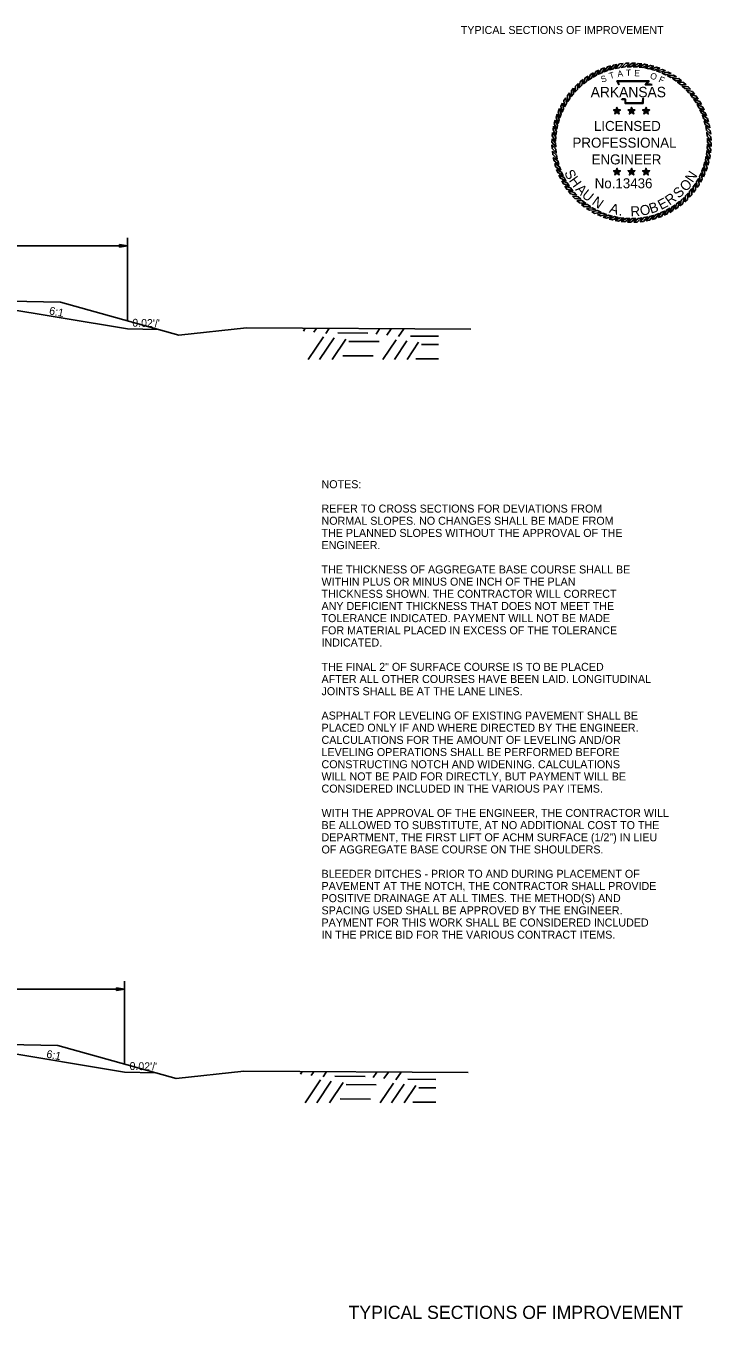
# Model space of a CAD drawing. Extents: x 1398565 to 1398920, y 1968324 to 1968581.
# Drawn here: x 1398868.6 to 1398919.9, y 1968325.3 to 1968422.2 of the extents above; entities that cross this region are included whole.
import ezdxf

# ---------------------------------------------------------------- set-up
doc = ezdxf.new("R2010")
doc.units = 0
for name, color, linetype in [('1', 7, 'Continuous'), ('10', 7, 'Continuous'), ('19', 7, 'Continuous'), ('42', 7, 'Continuous'), ('9', 7, 'Continuous'), ('G-ANNO-SYMB', 7, 'Continuous')]:
    doc.layers.add(name, color=color, linetype=linetype)

msp = doc.modelspace()

# ---------------------------------------------------------------- linework, layer by layer
at = {"layer": '19'}
for p, q in [((1398854.176, 1968405.693), (1398876.176, 1968405.693)), ((1398875.576, 1968405.588), (1398875.576, 1968405.798)), ((1398875.576, 1968405.798), (1398876.176, 1968405.693)), ((1398875.576, 1968405.743), (1398876.016, 1968405.708)), ((1398876.176, 1968405.693), (1398875.576, 1968405.588)), ((1398876.016, 1968405.678), (1398875.576, 1968405.638)), ((1398876.176, 1968400.085), (1398876.176, 1968406.293)), ((1398862.176, 1968401.81), (1398876.176, 1968399.477)), ((1398878.492, 1968399.431), (1398876.176, 1968399.477)), ((1398875.969, 1968344.375), (1398875.969, 1968350.582)), ((1398853.969, 1968349.982), (1398875.969, 1968349.982)), ((1398875.369, 1968349.877), (1398875.369, 1968350.087)), ((1398875.369, 1968350.087), (1398875.969, 1968349.982)), ((1398875.369, 1968350.032), (1398875.809, 1968349.997)), ((1398875.969, 1968349.982), (1398875.369, 1968349.877)), ((1398875.809, 1968349.967), (1398875.369, 1968349.927)), ((1398861.969, 1968346.1), (1398875.969, 1968343.767)), ((1398878.286, 1968343.72), (1398875.969, 1968343.767))]:
    msp.add_line(p, q, dxfattribs=at)
at = {"layer": '42'}
for points in [[(1398854.176, 1968401.924), (1398862.261, 1968401.64), (1398871.176, 1968401.464), (1398880.031, 1968399.003), (1398885.112, 1968399.545), (1398901.928, 1968399.456)], [(1398853.969, 1968346.213), (1398862.054, 1968345.93), (1398870.969, 1968345.753), (1398879.824, 1968343.293), (1398884.905, 1968343.835), (1398901.722, 1968343.746)]]:
    msp.add_lwpolyline(points, dxfattribs=at)
at = {"layer": '9'}
for p, q in [((1398889.366, 1968399.313), (1398889.469, 1968399.467)), ((1398889.715, 1968397.173), (1398890.868, 1968398.889)), ((1398890.163, 1968399.221), (1398890.329, 1968399.468)), ((1398890.575, 1968397.174), (1398891.666, 1968398.797)), ((1398891.053, 1968399.13), (1398891.282, 1968399.47)), ((1398891.527, 1968397.176), (1398892.556, 1968398.706)), ((1398891.943, 1968399.169), (1398894.205, 1968399.154)), ((1398894.817, 1968399.081), (1398895.083, 1968399.477)), ((1398895.328, 1968397.183), (1398896.32, 1968398.657)), ((1398895.615, 1968398.99), (1398895.943, 1968399.478)), ((1398896.505, 1968398.899), (1398896.895, 1968399.48)), ((1398897.394, 1968398.937), (1398899.5, 1968398.924)), ((1398892.779, 1968398.54), (1398895.041, 1968398.525)), ((1398896.188, 1968397.184), (1398897.117, 1968398.566)), ((1398897.141, 1968397.186), (1398898.007, 1968398.475)), ((1398898.23, 1968398.308), (1398899.501, 1968398.3)), ((1398892.336, 1968397.463), (1398894.597, 1968397.449)), ((1398897.787, 1968397.231), (1398899.503, 1968397.22)), ((1398889.159, 1968343.603), (1398889.263, 1968343.757)), ((1398889.957, 1968343.511), (1398890.123, 1968343.758)), ((1398890.847, 1968343.42), (1398891.075, 1968343.76)), ((1398891.737, 1968343.459), (1398893.999, 1968343.444)), ((1398894.611, 1968343.371), (1398894.876, 1968343.766)), ((1398895.408, 1968343.28), (1398895.736, 1968343.768)), ((1398896.298, 1968343.188), (1398896.689, 1968343.769)), ((1398889.508, 1968341.463), (1398890.662, 1968343.179)), ((1398890.368, 1968341.464), (1398891.459, 1968343.087)), ((1398891.321, 1968341.466), (1398892.349, 1968342.996)), ((1398892.572, 1968342.829), (1398894.834, 1968342.815)), ((1398895.122, 1968341.472), (1398896.113, 1968342.947)), ((1398895.982, 1968341.474), (1398896.911, 1968342.855)), ((1398896.934, 1968341.476), (1398897.801, 1968342.764)), ((1398897.188, 1968343.227), (1398899.294, 1968343.213)), ((1398898.023, 1968342.598), (1398899.295, 1968342.59)), ((1398892.129, 1968341.753), (1398894.391, 1968341.738)), ((1398897.58, 1968341.521), (1398899.297, 1968341.51))]:
    msp.add_line(p, q, dxfattribs=at)
at = {"layer": 'G-ANNO-SYMB'}
for points in [[(1398911.959, 1968419.05), (1398911.719, 1968418.958), (1398911.494, 1968418.56), (1398911.746, 1968418.674)], [(1398912.406, 1968419.19), (1398912.16, 1968419.117), (1398911.904, 1968418.738), (1398912.165, 1968418.832)], [(1398912.862, 1968419.294), (1398912.611, 1968419.241), (1398912.327, 1968418.883), (1398912.594, 1968418.957)], [(1398913.326, 1968419.362), (1398913.071, 1968419.329), (1398912.76, 1968418.995), (1398913.032, 1968419.047)], [(1398913.793, 1968419.394), (1398913.537, 1968419.381), (1398913.2, 1968419.072), (1398913.475, 1968419.103)], [(1398914.262, 1968419.389), (1398914.005, 1968419.396), (1398913.645, 1968419.115), (1398913.922, 1968419.124)], [(1398914.728, 1968419.347), (1398914.473, 1968419.375), (1398914.092, 1968419.122), (1398914.369, 1968419.109)], [(1398915.19, 1968419.269), (1398914.938, 1968419.316), (1398914.538, 1968419.095), (1398914.813, 1968419.06)], [(1398915.644, 1968419.155), (1398915.397, 1968419.222), (1398914.981, 1968419.032), (1398915.252, 1968418.976)], [(1398916.088, 1968419.005), (1398915.847, 1968419.092), (1398915.417, 1968418.935), (1398915.683, 1968418.858)], [(1398910.321, 1968418.155), (1398910.121, 1968417.994), (1398910.03, 1968417.546), (1398910.235, 1968417.732)], [(1398910.702, 1968418.426), (1398910.491, 1968418.281), (1398910.365, 1968417.842), (1398910.584, 1968418.012)], [(1398911.104, 1968418.667), (1398910.882, 1968418.539), (1398910.722, 1968418.111), (1398910.953, 1968418.263)], [(1398911.524, 1968418.875), (1398911.292, 1968418.765), (1398911.099, 1968418.351), (1398911.342, 1968418.484)], [(1398916.519, 1968418.822), (1398916.285, 1968418.926), (1398915.844, 1968418.804), (1398916.104, 1968418.706)], [(1398916.934, 1968418.604), (1398916.709, 1968418.727), (1398916.26, 1968418.64), (1398916.511, 1968418.522)], [(1398917.331, 1968418.355), (1398917.116, 1968418.496), (1398916.662, 1968418.444), (1398916.903, 1968418.307)], [(1398917.707, 1968418.076), (1398917.504, 1968418.233), (1398917.047, 1968418.217), (1398917.276, 1968418.061)], [(1398909.318, 1968417.174), (1398909.162, 1968416.971), (1398909.178, 1968416.514), (1398909.333, 1968416.743)], [(1398909.626, 1968417.527), (1398909.454, 1968417.337), (1398909.434, 1968416.88), (1398909.608, 1968417.096)], [(1398909.961, 1968417.855), (1398909.775, 1968417.678), (1398909.719, 1968417.224), (1398909.909, 1968417.427)], [(1398918.06, 1968417.768), (1398917.87, 1968417.94), (1398917.413, 1968417.96), (1398917.629, 1968417.787)], [(1398918.388, 1968417.433), (1398918.212, 1968417.62), (1398917.758, 1968417.675), (1398917.96, 1968417.486)], [(1398918.688, 1968417.074), (1398918.527, 1968417.274), (1398918.079, 1968417.365), (1398918.266, 1968417.16)], [(1398918.959, 1968416.692), (1398918.815, 1968416.904), (1398918.375, 1968417.03), (1398918.545, 1968416.811)], [(1398908.79, 1968416.401), (1398908.667, 1968416.176), (1398908.754, 1968415.727), (1398908.872, 1968415.978)], [(1398909.039, 1968416.798), (1398908.899, 1968416.583), (1398908.95, 1968416.129), (1398909.088, 1968416.37)], [(1398912.873, 1968415.806), (1398912.934, 1968415.891), (1398912.873, 1968416.079), (1398912.812, 1968415.891)], [(1398913.964, 1968415.806), (1398914.025, 1968415.891), (1398913.964, 1968416.079), (1398913.903, 1968415.891)], [(1398915.055, 1968415.806), (1398915.116, 1968415.891), (1398915.055, 1968416.079), (1398914.993, 1968415.891)], [(1398919.2, 1968416.29), (1398919.072, 1968416.512), (1398918.644, 1968416.672), (1398918.796, 1968416.441)], [(1398919.408, 1968415.87), (1398919.298, 1968416.102), (1398918.884, 1968416.295), (1398919.017, 1968416.052)], [(1398908.239, 1968415.111), (1398908.172, 1968414.864), (1398908.362, 1968414.447), (1398908.418, 1968414.719)], [(1398908.389, 1968415.555), (1398908.303, 1968415.314), (1398908.459, 1968414.884), (1398908.536, 1968415.15)], [(1398908.573, 1968415.986), (1398908.468, 1968415.752), (1398908.59, 1968415.311), (1398908.688, 1968415.571)], [(1398912.873, 1968415.806), (1398912.812, 1968415.891), (1398912.613, 1968415.891), (1398912.774, 1968415.774)], [(1398912.873, 1968415.806), (1398912.774, 1968415.774), (1398912.713, 1968415.586), (1398912.873, 1968415.702)], [(1398912.873, 1968415.806), (1398912.972, 1968415.774), (1398913.132, 1968415.891), (1398912.934, 1968415.891)], [(1398912.873, 1968415.806), (1398912.873, 1968415.702), (1398913.033, 1968415.586), (1398912.972, 1968415.774)], [(1398913.964, 1968415.806), (1398913.903, 1968415.891), (1398913.704, 1968415.891), (1398913.865, 1968415.774)], [(1398913.964, 1968415.806), (1398913.865, 1968415.774), (1398913.803, 1968415.586), (1398913.964, 1968415.702)], [(1398913.964, 1968415.806), (1398914.063, 1968415.774), (1398914.223, 1968415.891), (1398914.025, 1968415.891)], [(1398913.964, 1968415.806), (1398913.964, 1968415.702), (1398914.124, 1968415.586), (1398914.063, 1968415.774)], [(1398915.055, 1968415.806), (1398914.993, 1968415.891), (1398914.795, 1968415.891), (1398914.956, 1968415.774)], [(1398915.055, 1968415.806), (1398914.956, 1968415.774), (1398914.894, 1968415.586), (1398915.055, 1968415.702)], [(1398915.055, 1968415.806), (1398915.154, 1968415.774), (1398915.314, 1968415.891), (1398915.116, 1968415.891)], [(1398915.055, 1968415.806), (1398915.055, 1968415.702), (1398915.215, 1968415.586), (1398915.154, 1968415.774)], [(1398919.583, 1968415.436), (1398919.491, 1968415.675), (1398919.093, 1968415.9), (1398919.207, 1968415.648)], [(1398919.723, 1968414.989), (1398919.65, 1968415.235), (1398919.271, 1968415.49), (1398919.365, 1968415.23)], [(1398908.047, 1968414.195), (1398908.02, 1968413.94), (1398908.272, 1968413.559), (1398908.285, 1968413.836)], [(1398908.125, 1968414.657), (1398908.078, 1968414.405), (1398908.3, 1968414.005), (1398908.334, 1968414.28)], [(1398919.827, 1968414.532), (1398919.774, 1968414.783), (1398919.417, 1968415.068), (1398919.49, 1968414.8)], [(1398919.895, 1968414.068), (1398919.863, 1968414.323), (1398919.528, 1968414.635), (1398919.58, 1968414.362)], [(1398919.927, 1968413.601), (1398919.914, 1968413.857), (1398919.605, 1968414.194), (1398919.636, 1968413.919)], [(1398908.005, 1968413.728), (1398907.998, 1968413.472), (1398908.279, 1968413.112), (1398908.271, 1968413.389)], [(1398908, 1968413.26), (1398908.013, 1968413.004), (1398908.322, 1968412.667), (1398908.292, 1968412.942)], [(1398919.881, 1968412.666), (1398919.908, 1968412.921), (1398919.656, 1968413.302), (1398919.643, 1968413.026)], [(1398919.922, 1968413.133), (1398919.93, 1968413.389), (1398919.648, 1968413.749), (1398919.657, 1968413.472)], [(1398908.032, 1968412.793), (1398908.065, 1968412.538), (1398908.399, 1968412.226), (1398908.347, 1968412.499)], [(1398908.1, 1968412.329), (1398908.153, 1968412.078), (1398908.511, 1968411.794), (1398908.438, 1968412.061)], [(1398919.688, 1968411.75), (1398919.755, 1968411.998), (1398919.565, 1968412.414), (1398919.509, 1968412.142)], [(1398919.802, 1968412.204), (1398919.85, 1968412.456), (1398919.628, 1968412.856), (1398919.593, 1968412.581)], [(1398908.205, 1968411.873), (1398908.277, 1968411.626), (1398908.656, 1968411.371), (1398908.562, 1968411.632)], [(1398908.345, 1968411.426), (1398908.436, 1968411.186), (1398908.834, 1968410.961), (1398908.72, 1968411.213)], [(1398912.873, 1968411.238), (1398912.812, 1968411.322), (1398912.613, 1968411.322), (1398912.774, 1968411.206)], [(1398912.873, 1968411.238), (1398912.774, 1968411.206), (1398912.713, 1968411.017), (1398912.873, 1968411.134)], [(1398912.873, 1968411.238), (1398912.934, 1968411.322), (1398912.873, 1968411.511), (1398912.812, 1968411.322)], [(1398912.873, 1968411.238), (1398912.972, 1968411.206), (1398913.132, 1968411.322), (1398912.934, 1968411.322)], [(1398912.873, 1968411.238), (1398912.873, 1968411.134), (1398913.033, 1968411.017), (1398912.972, 1968411.206)], [(1398913.964, 1968411.238), (1398913.903, 1968411.322), (1398913.704, 1968411.322), (1398913.865, 1968411.206)], [(1398913.964, 1968411.238), (1398913.865, 1968411.206), (1398913.803, 1968411.017), (1398913.964, 1968411.134)], [(1398913.964, 1968411.238), (1398914.025, 1968411.322), (1398913.964, 1968411.511), (1398913.903, 1968411.322)], [(1398913.964, 1968411.238), (1398914.063, 1968411.206), (1398914.223, 1968411.322), (1398914.025, 1968411.322)], [(1398913.964, 1968411.238), (1398913.964, 1968411.134), (1398914.124, 1968411.017), (1398914.063, 1968411.206)], [(1398915.055, 1968411.238), (1398914.993, 1968411.322), (1398914.795, 1968411.322), (1398914.956, 1968411.206)], [(1398915.055, 1968411.238), (1398914.956, 1968411.206), (1398914.894, 1968411.017), (1398915.055, 1968411.134)], [(1398915.055, 1968411.238), (1398915.116, 1968411.322), (1398915.055, 1968411.511), (1398914.993, 1968411.322)], [(1398915.055, 1968411.238), (1398915.154, 1968411.206), (1398915.314, 1968411.322), (1398915.116, 1968411.322)], [(1398915.055, 1968411.238), (1398915.055, 1968411.134), (1398915.215, 1968411.017), (1398915.154, 1968411.206)], [(1398919.355, 1968410.875), (1398919.46, 1968411.109), (1398919.337, 1968411.55), (1398919.239, 1968411.291)], [(1398919.539, 1968411.306), (1398919.625, 1968411.548), (1398919.468, 1968411.977), (1398919.391, 1968411.711)], [(1398908.519, 1968410.991), (1398908.629, 1968410.759), (1398909.044, 1968410.566), (1398908.91, 1968410.809)], [(1398908.728, 1968410.571), (1398908.855, 1968410.349), (1398909.284, 1968410.189), (1398909.131, 1968410.42)], [(1398918.609, 1968409.687), (1398918.766, 1968409.89), (1398918.75, 1968410.347), (1398918.594, 1968410.118)], [(1398918.889, 1968410.063), (1398919.029, 1968410.278), (1398918.977, 1968410.732), (1398918.84, 1968410.492)], [(1398919.138, 1968410.46), (1398919.26, 1968410.685), (1398919.173, 1968411.134), (1398919.055, 1968410.883)], [(1398908.968, 1968410.169), (1398909.113, 1968409.958), (1398909.553, 1968409.831), (1398909.383, 1968410.05)], [(1398909.239, 1968409.787), (1398909.4, 1968409.588), (1398909.848, 1968409.496), (1398909.662, 1968409.701)], [(1398909.54, 1968409.428), (1398909.716, 1968409.241), (1398910.17, 1968409.186), (1398909.968, 1968409.375)], [(1398917.607, 1968408.706), (1398917.807, 1968408.867), (1398917.898, 1968409.315), (1398917.693, 1968409.129)], [(1398917.966, 1968409.007), (1398918.153, 1968409.183), (1398918.209, 1968409.637), (1398918.019, 1968409.435)], [(1398918.301, 1968409.334), (1398918.473, 1968409.525), (1398918.493, 1968409.981), (1398918.32, 1968409.765)], [(1398909.867, 1968409.093), (1398910.058, 1968408.921), (1398910.515, 1968408.901), (1398910.298, 1968409.074)], [(1398910.22, 1968408.785), (1398910.424, 1968408.629), (1398910.881, 1968408.644), (1398910.651, 1968408.8)], [(1398910.596, 1968408.506), (1398910.811, 1968408.366), (1398911.266, 1968408.417), (1398911.025, 1968408.555)], [(1398910.993, 1968408.257), (1398911.218, 1968408.134), (1398911.667, 1968408.221), (1398911.416, 1968408.339)], [(1398915.969, 1968407.812), (1398916.208, 1968407.903), (1398916.434, 1968408.301), (1398916.181, 1968408.187)], [(1398916.403, 1968407.986), (1398916.635, 1968408.096), (1398916.828, 1968408.511), (1398916.586, 1968408.377)], [(1398916.823, 1968408.194), (1398917.046, 1968408.322), (1398917.206, 1968408.751), (1398916.974, 1968408.598)], [(1398917.225, 1968408.435), (1398917.437, 1968408.58), (1398917.563, 1968409.019), (1398917.344, 1968408.849)], [(1398911.408, 1968408.04), (1398911.642, 1968407.935), (1398912.083, 1968408.057), (1398911.824, 1968408.155)], [(1398911.839, 1968407.856), (1398912.081, 1968407.77), (1398912.51, 1968407.926), (1398912.244, 1968408.003)], [(1398912.283, 1968407.706), (1398912.531, 1968407.639), (1398912.947, 1968407.829), (1398912.675, 1968407.885)], [(1398912.737, 1968407.592), (1398912.99, 1968407.545), (1398913.389, 1968407.766), (1398913.114, 1968407.801)], [(1398913.199, 1968407.514), (1398913.454, 1968407.486), (1398913.836, 1968407.739), (1398913.559, 1968407.752)], [(1398913.666, 1968407.472), (1398913.922, 1968407.465), (1398914.283, 1968407.746), (1398914.006, 1968407.738)], [(1398914.134, 1968407.467), (1398914.39, 1968407.48), (1398914.728, 1968407.789), (1398914.452, 1968407.758)], [(1398914.602, 1968407.499), (1398914.856, 1968407.532), (1398915.168, 1968407.866), (1398914.896, 1968407.814)], [(1398915.065, 1968407.567), (1398915.316, 1968407.62), (1398915.601, 1968407.978), (1398915.333, 1968407.905)], [(1398915.522, 1968407.672), (1398915.768, 1968407.744), (1398916.024, 1968408.123), (1398915.763, 1968408.029)]]:
    msp.add_lwpolyline(points, close=True, dxfattribs=at)
for points in [[(1398913.008, 1968417.761), (1398912.869, 1968418.062), (1398915.275, 1968418.063), (1398915.074, 1968417.811), (1398915.238, 1968417.813), (1398915.374, 1968417.814), (1398915.511, 1968417.8)], [(1398913.043, 1968417.777), (1398912.928, 1968418.024), (1398915.196, 1968418.025), (1398914.994, 1968417.771), (1398915.238, 1968417.775), (1398915.372, 1968417.776), (1398915.507, 1968417.762)], [(1398914.896, 1968416.752), (1398914.855, 1968416.719), (1398914.841, 1968416.669), (1398914.828, 1968416.544), (1398914.828, 1968416.378), (1398913.484, 1968416.378), (1398913.484, 1968416.602), (1398913.484, 1968416.652), (1398913.43, 1968416.669), (1398913.239, 1968416.669), (1398913.205, 1968416.721)], [(1398914.872, 1968416.782), (1398914.821, 1968416.741), (1398914.804, 1968416.676), (1398914.79, 1968416.546), (1398914.79, 1968416.416), (1398913.523, 1968416.416), (1398913.523, 1968416.602), (1398913.523, 1968416.68), (1398913.436, 1968416.707), (1398913.26, 1968416.707), (1398913.237, 1968416.742)]]:
    msp.add_lwpolyline(points, dxfattribs=at)

# ---------------------------------------------------------------- texts
at = {"layer": '1'}
msp.add_text('TYPICAL SECTIONS OF IMPROVEMENT', height=0.6, dxfattribs=at).set_placement((1398901.166, 1968421.577))
at = {"layer": '10'}
for p in [(1398870.279, 1968400.574), (1398870.072, 1968344.864)]:
    msp.add_text('6:1', height=0.59, rotation=348.76163, dxfattribs=at).set_placement(p)
at = {"layer": '19'}
for p in [(1398876.543, 1968399.642), (1398876.337, 1968343.932)]:
    msp.add_text("0.02'/'", height=0.59, rotation=358.85424, dxfattribs=at).set_placement(p)
for s, height, p in [('NOTES:', 0.6, (1398890.728, 1968387.53)), ('REFER TO CROSS SECTIONS FOR DEVIATIONS FROM', 0.6, (1398890.728, 1968385.705)), ('NORMAL SLOPES. NO CHANGES SHALL BE MADE FROM ', 0.6, (1398890.728, 1968384.792)), ('THE PLANNED SLOPES WITHOUT THE APPROVAL OF THE', 0.6, (1398890.728, 1968383.88)), ('ENGINEER.', 0.6, (1398890.728, 1968382.967)), ('THE THICKNESS OF AGGREGATE BASE COURSE SHALL BE', 0.6, (1398890.728, 1968381.142)), ('WITHIN PLUS OR MINUS ONE INCH OF THE PLAN ', 0.6, (1398890.728, 1968380.23)), ('THICKNESS SHOWN. THE CONTRACTOR WILL CORRECT', 0.6, (1398890.728, 1968379.317)), ('ANY DEFICIENT THICKNESS THAT DOES NOT MEET THE', 0.6, (1398890.728, 1968378.405)), ('TOLERANCE INDICATED. PAYMENT WILL NOT BE MADE', 0.6, (1398890.728, 1968377.492)), ('FOR MATERIAL PLACED IN EXCESS OF THE TOLERANCE', 0.6, (1398890.728, 1968376.58)), ('INDICATED.', 0.6, (1398890.728, 1968375.667)), ('THE FINAL 2" OF SURFACE COURSE IS TO BE PLACED', 0.6, (1398890.728, 1968373.842)), ('AFTER ALL OTHER COURSES HAVE BEEN LAID. LONGITUDINAL', 0.6, (1398890.728, 1968372.93)), ('JOINTS SHALL BE AT THE LANE LINES.', 0.6, (1398890.728, 1968372.017)), ('ASPHALT FOR LEVELING OF EXISTING PAVEMENT SHALL BE', 0.6, (1398890.728, 1968370.192)), ('PLACED ONLY IF AND WHERE DIRECTED BY THE ENGINEER.', 0.6, (1398890.728, 1968369.28)), ('CALCULATIONS FOR THE AMOUNT OF LEVELING AND/OR', 0.6, (1398890.728, 1968368.367)), ('LEVELING OPERATIONS SHALL BE PERFORMED BEFORE ', 0.6, (1398890.728, 1968367.455)), ('CONSTRUCTING NOTCH AND WIDENING. CALCULATIONS', 0.6, (1398890.728, 1968366.542)), ('WILL NOT BE PAID FOR DIRECTLY, BUT PAYMENT WILL BE', 0.6, (1398890.728, 1968365.63)), ('CONSIDERED INCLUDED IN THE VARIOUS PAY ITEMS.', 0.6, (1398890.728, 1968364.717)), ('WITH THE APPROVAL OF THE ENGINEER, THE CONTRACTOR WILL', 0.6, (1398890.728, 1968362.892)), ('BE ALLOWED TO SUBSTITUTE, AT NO ADDITIONAL COST TO THE', 0.6, (1398890.728, 1968361.98)), ('DEPARTMENT, THE FIRST LIFT OF ACHM SURFACE (1/2") IN LIEU', 0.6, (1398890.728, 1968361.067)), ('OF AGGREGATE BASE COURSE ON THE SHOULDERS.', 0.6, (1398890.728, 1968360.155)), ('BLEEDER DITCHES - PRIOR TO AND DURING PLACEMENT OF', 0.6, (1398890.728, 1968358.33)), ('PAVEMENT AT THE NOTCH, THE CONTRACTOR SHALL PROVIDE', 0.6, (1398890.728, 1968357.417)), ('POSITIVE DRAINAGE AT ALL TIMES. THE METHOD(S) AND', 0.6, (1398890.728, 1968356.505)), ('SPACING USED SHALL BE APPROVED BY THE ENGINEER.', 0.6, (1398890.728, 1968355.592)), ('PAYMENT FOR THIS WORK SHALL BE CONSIDERED INCLUDED', 0.6, (1398890.728, 1968354.68)), ('IN THE PRICE BID FOR THE VARIOUS CONTRACT ITEMS.', 0.6, (1398890.728, 1968353.767)), ('TYPICAL SECTIONS OF IMPROVEMENT', 0.98999, (1398892.754, 1968325.265))]:
    msp.add_text(s, height=height, dxfattribs=at).set_placement(p)
at = {"layer": 'G-ANNO-SYMB'}
for s, height, rotation, p in [('S', 0.475, 19.77256, (1398911.755, 1968417.918)), ('T', 0.475, 16.90148, (1398912.358, 1968418.189)), ('A', 0.475, 8.67877, (1398912.935, 1968418.34)), ('T', 0.475, 1.47887, (1398913.548, 1968418.434)), ('E', 0.475, 356.67203, (1398914.155, 1968418.42)), ('O', 0.475, 341.2218, (1398915.308, 1968418.257)), ('F', 0.475, 335.36282, (1398915.947, 1968418.007)), ('ARKANSAS', 0.7747, 360, (1398910.902, 1968416.839)), ('LICENSED', 0.75, 360, (1398911.142, 1968414.31)), ('PROFESSIONAL', 0.75, 360, (1398909.535, 1968413.056)), ('ENGINEER', 0.75, 360, (1398910.964, 1968411.801)), ('S', 0.75, 298.16364, (1398908.896, 1968411.171)), ('N', 0.75, 56.10067, (1398918.538, 1968410.387)), ('H', 0.75, 305.61905, (1398909.238, 1968410.583)), ('No.13436', 0.747, 360, (1398911.2, 1968410.013)), ('O', 0.75, 44.77573, (1398918.017, 1968409.712)), ('A', 0.75, 313.44722, (1398909.714, 1968409.898)), ('U', 0.75, 320.90262, (1398910.181, 1968409.409)), ('N', 0.75, 324.93262, (1398910.937, 1968408.851)), ('E', 0.75, 27.83149, (1398916.178, 1968408.373)), ('R', 0.75, 35.65967, (1398916.812, 1968408.705)), ('S', 0.75, 43.48784, (1398917.502, 1968409.214)), ('A', 0.75, 343.09908, (1398912.245, 1968408.207)), ('R', 0.75, 3.22866, (1398913.901, 1968407.894)), ('O', 0.75, 11.42961, (1398914.669, 1968407.942)), ('B', 0.75, 18.88501, (1398915.421, 1968408.102)), ('.', 0.75, 351.30002, (1398912.982, 1968407.989))]:
    msp.add_text(s, height=height, rotation=rotation, dxfattribs=at).set_placement(p)

doc.saveas('drawing.dxf')
